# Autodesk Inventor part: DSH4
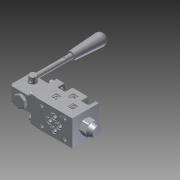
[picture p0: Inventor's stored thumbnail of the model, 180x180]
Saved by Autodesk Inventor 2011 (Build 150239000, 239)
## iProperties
Created: 2012-01
Part Number: DSH4
Document SubType Name: Modeling
Designer: khramov
Density: 1 g/cm^3
Author: khramov
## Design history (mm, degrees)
derived "DSH3_S1_11N.iam"
node "Твердое тело1"
node "0144168_.ipt:1"
node "0144430_.ipt:1"
sketch "0532115_UNI_5931___M5x16.ipt:1"
sketch "0532115_UNI_5931___M5x16.ipt:2"
sketch "0532115_UNI_5931___M5x16.ipt:3"
sketch "0532115_UNI_5931___M5x16.ipt:4"
sketch "0144191_.ipt:1"
sketch "0144197.ipt:1"
sketch "0630119.ipt:1"
sketch "0144429_.ipt:1"
node "0144194_.ipt:1"
sketch "3001630001_.ipt:1"
